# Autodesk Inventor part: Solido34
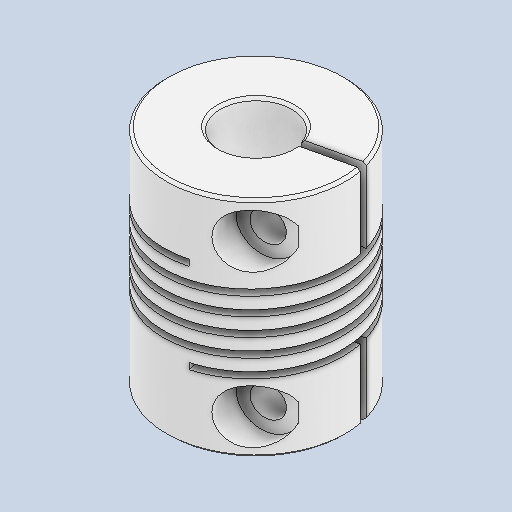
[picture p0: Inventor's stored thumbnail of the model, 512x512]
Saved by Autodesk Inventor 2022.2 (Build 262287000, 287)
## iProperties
Created: 2024-10
Part Number: Solido34
Material: Generico
Document SubType Name: Modeling
Designer: 18907419
Density: 1 g/cm^3
Appearance: Default
Author: 18907419
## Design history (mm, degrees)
feature "Solido34"
node "Solido1"
